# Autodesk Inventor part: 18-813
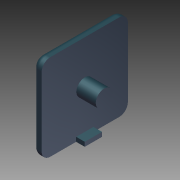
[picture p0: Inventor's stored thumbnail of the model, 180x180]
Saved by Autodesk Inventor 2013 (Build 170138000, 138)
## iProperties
Created: 2006-02
Part Number: 18-813
Material: Glass Filled Nylon
Description: END CAP, 40 SERIES, 40x40
Document SubType Name: Modeling
Designer: Autodesk, Inc.
Manufacturer: Standard
Standards Organization: Custom
Catalog Web Link: http://www.parker.com/ead/cm1.asp?cmid=809
Vendor: PARKER IPS
Mass: 7.50143 g
Surface Area: 39.1851 cm^2
Volume: 6.63843 cm^3
Density: 1.13 g/cm^3
Author: Autodesk, Inc.
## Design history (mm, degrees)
derived "18-xxx 40 Series End Caps.ipt"
body "Solid1"
tag "TaggingFeature2"
feature "Solid1::18-xxx 40 Series End Caps.ipt" dims "ScaleForDerivedMember" = 10
